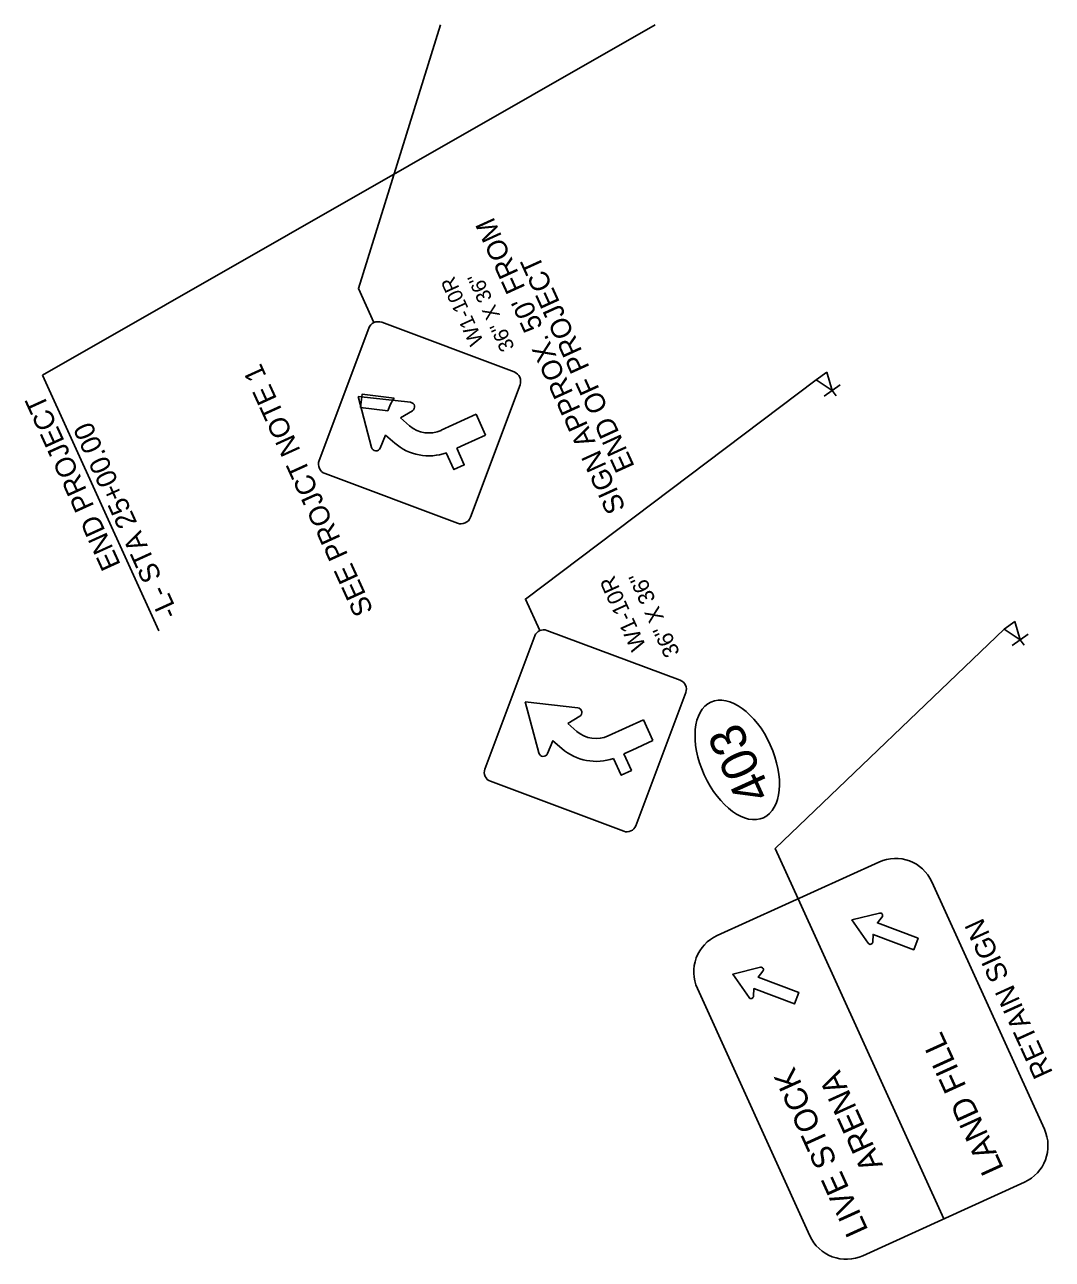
# Model space of a CAD drawing. Extents: x 2096999 to 2102576, y 682920 to 687015.
# Drawn here: x 2101573.8 to 2101932.4, y 683918.8 to 684349.7 of the extents above; entities that cross this region are included whole.
import ezdxf

# ---------------------------------------------------------------- set-up
doc = ezdxf.new("R2010")
doc.units = 0
doc.layers.add('Default', color=7, linetype='Continuous')
doc.layers.add('Prop Horizontal Alignment Station Label', color=7, linetype='Continuous')

msp = doc.modelspace()

# ---------------------------------------------------------------- linework, layer by layer
at = {"layer": 'Default'}
for p, q in [((2101693.88, 684243.79), (2101676.56, 684197.58)), ((2101744.62, 684228.53), (2101698.41, 684245.85)), ((2101850.01, 684225.82), (2101853.73, 684228.49)), ((2101855.64, 684222.11), (2101850.01, 684225.82)), ((2101853.73, 684228.49), (2101855.64, 684222.11)), ((2101729.36, 684177.79), (2101746.68, 684224)), ((2101852.85, 684220.11), (2101858.38, 684224.08)), ((2101855.64, 684222.11), (2101856.99, 684220.23)), ((2101690.14, 684220.01), (2101708.49, 684217.93)), ((2101694.88, 684202.17), (2101690.14, 684220.01)), ((2101708.49, 684217.93), (2101690.14, 684220.01)), ((2101690.14, 684220.01), (2101694.88, 684202.17)), ((2101708.49, 684217.93), (2101690.14, 684220.01)), ((2101690.14, 684220.01), (2101694.88, 684202.17)), ((2101709.14, 684214.99), (2101704.99, 684212.47)), ((2101704.99, 684212.47), (2101709.14, 684214.99)), ((2101704.99, 684212.47), (2101709.14, 684214.99)), ((2101704.99, 684212.47), (2101708.15, 684209.72)), ((2101708.15, 684209.72), (2101704.99, 684212.47)), ((2101708.15, 684209.72), (2101704.99, 684212.47)), ((2101719.11, 684208.15), (2101731.38, 684213.74)), ((2101731.38, 684213.74), (2101719.11, 684208.15)), ((2101731.38, 684213.74), (2101719.11, 684208.15)), ((2101731.38, 684213.74), (2101734.68, 684206.48)), ((2101734.68, 684206.48), (2101731.38, 684213.74)), ((2101734.68, 684206.48), (2101731.38, 684213.74)), ((2101697.88, 684201.95), (2101699.78, 684206.44)), ((2101699.78, 684206.44), (2101702.94, 684203.69)), ((2101708.99, 684207.72), (2101708.98, 684207.7)), ((2101734.68, 684206.48), (2101727.4, 684203.16)), ((2101727.4, 684203.16), (2101734.68, 684206.48)), ((2101727.4, 684203.16), (2101734.68, 684206.48)), ((2101694.88, 684202.17), (2101694.88, 684202.17)), ((2101694.88, 684202.17), (2101694.88, 684202.17)), ((2101694.88, 684202.17), (2101694.88, 684202.17)), ((2101727.4, 684203.16), (2101724.57, 684201.87)), ((2101724.57, 684201.87), (2101727.4, 684203.16)), ((2101724.57, 684201.87), (2101727.4, 684203.16)), ((2101678.62, 684193.05), (2101724.83, 684175.73)), ((2101915.59, 684138.73), (2101919.31, 684141.4)), ((2101919.31, 684141.4), (2101921.22, 684135.02)), ((2101802.6, 684120.9), (2101756.07, 684138.34)), ((2101921.22, 684135.02), (2101915.59, 684138.73)), ((2101918.43, 684133.02), (2101923.96, 684136.99)), ((2101921.22, 684135.02), (2101922.57, 684133.14)), ((2101753.24, 684095.53), (2101748.5, 684113.36)), ((2101748.5, 684113.36), (2101766.85, 684111.28)), ((2101766.85, 684111.28), (2101748.5, 684113.36)), ((2101748.5, 684113.36), (2101753.24, 684095.53)), ((2101767.5, 684108.34), (2101763.35, 684105.82)), ((2101763.35, 684105.82), (2101767.5, 684108.34)), ((2101763.35, 684105.82), (2101766.51, 684103.08)), ((2101766.51, 684103.08), (2101763.35, 684105.82)), ((2101777.47, 684101.51), (2101789.74, 684107.09)), ((2101789.74, 684107.09), (2101777.47, 684101.51)), ((2101789.74, 684107.09), (2101793.04, 684099.84)), ((2101793.04, 684099.84), (2101789.74, 684107.09)), ((2101767.35, 684101.08), (2101767.34, 684101.05)), ((2101785.76, 684096.52), (2101782.93, 684095.23)), ((2101782.93, 684095.23), (2101785.76, 684096.52)), ((2101793.04, 684099.84), (2101785.76, 684096.52)), ((2101785.76, 684096.52), (2101793.04, 684099.84)), ((2101753.24, 684095.52), (2101753.24, 684095.53)), ((2101753.24, 684095.53), (2101753.24, 684095.52)), ((2101843.71, 684044.64), (2101835.75, 684062.14)), ((2101894.54, 683932.9), (2101843.71, 684044.64))]:
    msp.add_line(p, q, dxfattribs=at)
for points in [[(2101695.71, 684245.76), (2101690.3, 684257.66), (2101718.91, 684349.73)], [(2101753.56, 684138.25), (2101748.57, 684149.24), (2101850.01, 684225.82)], [(2101702.7, 684219.42), (2101691.64, 684220.79), (2101691.06, 684216.14), (2101700.59, 684214.95)], [(2101702.94, 684203.69), (2101699.78, 684206.44), (2101697.88, 684201.95)], [(2101697.88, 684201.95), (2101699.78, 684206.44), (2101702.94, 684203.69)], [(2101720.96, 684200.3), (2101723.63, 684194.43), (2101727.21, 684196.06), (2101724.57, 684201.87)], [(2101720.96, 684200.3), (2101723.63, 684194.43), (2101727.21, 684196.06), (2101724.57, 684201.87)], [(2101720.96, 684200.3), (2101723.63, 684194.43), (2101727.21, 684196.06), (2101724.57, 684201.87)], [(2101751.85, 684136.42), (2101734.41, 684089.89)], [(2101835.75, 684062.14), (2101835.75, 684062.14), (2101915.59, 684138.73)], [(2101787.09, 684070.15), (2101804.52, 684116.68)], [(2101761.3, 684097.04), (2101758.14, 684099.79), (2101756.24, 684095.31)], [(2101756.24, 684095.31), (2101758.14, 684099.79), (2101761.3, 684097.04)], [(2101779.32, 684093.66), (2101781.99, 684087.79), (2101785.57, 684089.42), (2101782.93, 684095.23)], [(2101779.32, 684093.66), (2101781.99, 684087.79), (2101785.57, 684089.42), (2101782.93, 684095.23)], [(2101736.33, 684085.66), (2101782.86, 684068.23)], [(2101815.48, 684031.8), (2101871.95, 684057.48)], [(2101890.4, 684050.57), (2101929.69, 683964.19)], [(2101868.21, 684029.11), (2101862.5, 684037.25), (2101872.16, 684039.65)], [(2101868.21, 684029.11), (2101862.5, 684037.25), (2101872.16, 684039.65)], [(2101868.21, 684029.11), (2101862.5, 684037.25), (2101872.16, 684039.65)], [(2101873.04, 684038.29), (2101871.4, 684036.2), (2101885.58, 684030.89), (2101884.08, 684026.88), (2101869.9, 684032.2), (2101869.76, 684029.55)], [(2101873.04, 684038.29), (2101871.4, 684036.2), (2101885.58, 684030.89), (2101884.08, 684026.88), (2101869.9, 684032.2), (2101869.76, 684029.55)], [(2101873.04, 684038.29), (2101871.4, 684036.2), (2101885.58, 684030.89), (2101884.08, 684026.88), (2101869.9, 684032.2), (2101869.76, 684029.55)], [(2101826.61, 684010.19), (2101820.91, 684018.33), (2101830.56, 684020.73)], [(2101826.61, 684010.19), (2101820.91, 684018.33), (2101830.56, 684020.73)], [(2101826.61, 684010.19), (2101820.91, 684018.33), (2101830.56, 684020.73)], [(2101831.44, 684019.37), (2101829.81, 684017.28), (2101843.98, 684011.97), (2101842.48, 684007.96), (2101828.3, 684013.28), (2101828.17, 684010.63)], [(2101831.44, 684019.37), (2101829.81, 684017.28), (2101843.98, 684011.97), (2101842.48, 684007.96), (2101828.3, 684013.28), (2101828.17, 684010.63)], [(2101831.44, 684019.37), (2101829.81, 684017.28), (2101843.98, 684011.97), (2101842.48, 684007.96), (2101828.3, 684013.28), (2101828.17, 684010.63)], [(2101847.85, 683926.97), (2101808.57, 684013.35)], [(2101922.77, 683945.74), (2101866.3, 683920.06)]]:
    msp.add_lwpolyline(points, dxfattribs=at)
for centre, radius, start, end in [((2101697.17, 684242.55), 3.52, 69.458, 159.458), ((2101743.38, 684225.24), 3.52, 339.458, 69.458), ((2101718.47, 684209.24), 18.77, 147.1671, 162.2946), ((2101708.31, 684216.35), 1.59, 301.3774, 83.5059), ((2101708.31, 684216.35), 1.59, 301.3774, 83.5059), ((2101708.31, 684216.35), 1.59, 301.3774, 83.5059), ((2101714.86, 684217.48), 10.26, 229.1817, 294.4888), ((2101714.86, 684217.48), 10.26, 229.1817, 294.4888), ((2101714.86, 684217.48), 10.26, 229.1817, 294.4888), ((2101696.42, 684202.58), 1.59, 194.8575, 336.9795), ((2101696.42, 684202.58), 1.59, 194.8575, 336.9795), ((2101696.42, 684202.58), 1.59, 194.8575, 336.9795), ((2101714.86, 684217.48), 18.23, 229.1817, 289.562), ((2101714.86, 684217.48), 18.23, 229.1817, 289.562), ((2101714.86, 684217.48), 18.23, 229.1817, 289.562), ((2101679.86, 684196.34), 3.52, 159.458, 249.458), ((2101726.07, 684179.02), 3.52, 249.458, 339.458), ((2101754.92, 684135.26), 3.28, 69.458, 159.458), ((2101801.45, 684117.83), 3.28, 24.458, 69.458), ((2101801.45, 684117.83), 3.28, 339.458, 24.458), ((2101766.67, 684109.7), 1.59, 301.3774, 83.5059), ((2101766.67, 684109.7), 1.59, 301.3774, 83.5059), ((2101773.22, 684110.84), 10.26, 229.1817, 294.4888), ((2101773.22, 684110.84), 10.26, 229.1817, 294.4888), ((2101773.22, 684110.84), 18.23, 229.1817, 289.562), ((2101773.22, 684110.84), 18.23, 229.1817, 289.562), ((2101754.78, 684095.93), 1.59, 194.8575, 336.9795), ((2101754.78, 684095.93), 1.59, 194.8575, 336.9795), ((2101737.49, 684088.73), 3.28, 159.445, 204.4515), ((2101737.49, 684088.73), 3.28, 204.4515, 249.458), ((2101784.01, 684071.3), 3.28, 249.458, 339.458), ((2101877.72, 684044.8), 13.93, 24.458, 114.458), ((2101872.36, 684038.81), 0.856, 321.857, 103.9072), ((2101872.36, 684038.81), 0.856, 321.857, 103.9072), ((2101872.36, 684038.81), 0.856, 321.857, 103.9072), ((2101821.25, 684019.12), 13.93, 114.458, 204.458), ((2101868.91, 684029.6), 0.856, 215.0087, 357.0589), ((2101868.91, 684029.6), 0.856, 215.0087, 357.0589), ((2101868.91, 684029.6), 0.856, 215.0087, 357.0589), ((2101830.77, 684019.89), 0.856, 321.857, 103.9072), ((2101830.77, 684019.89), 0.856, 321.857, 103.9072), ((2101830.77, 684019.89), 0.856, 321.857, 103.9072), ((2101827.31, 684010.68), 0.856, 215.0087, 357.0589), ((2101827.31, 684010.68), 0.856, 215.0087, 357.0589), ((2101827.31, 684010.68), 0.856, 215.0087, 357.0589), ((2101917, 683958.42), 13.93, 294.458, 24.458), ((2101860.54, 683932.74), 13.93, 204.458, 294.458)]:
    msp.add_arc(centre, radius, start, end, dxfattribs=at)
msp.add_ellipse((2101822.49, 684093.13), major_axis=(9.17, -20.19), ratio=0.571429, dxfattribs=at)
at = {"layer": 'Prop Horizontal Alignment Station Label'}
for p in [(2101793.81, 684349.66), (2101620.61, 684138.18)]:
    msp.add_line(p, (2101580.03, 684227.41), dxfattribs=at)

# ---------------------------------------------------------------- texts
at = {"layer": 'Default'}
for s, height, rotation, p in [("SIGN APPROX. 50' FROM", 7, 114.4888, (2101783.68, 684180.97)), ('END OF PROJECT', 7, 114.4888, (2101786.8, 684195.53)), ('W1-10R', 5.174, 114.458, (2101734.05, 684239.19)), ("36'' X 36''", 5.1742, 114.458, (2101744.88, 684237.09)), ('SEE PROJCT NOTE 1', 7, 114.4888, (2101695.61, 684145.24)), ('W1-10R', 5.625, 114.458, (2101790.8, 684132.77)), ("36'' X 36''", 5.6251, 114.458, (2101802.58, 684130.49)), ('403', 12.516, 114.4239, (2101834.69, 684081.4)), ('RETAIN SIGN', 7, 114.4888, (2101932.76, 683983.93)), ('LAND FILL', 8, 114.458, (2101915.62, 683950.49)), ('LIVE STOCK', 8, 114.458, (2101868.33, 683928.99)), ('ARENA', 8, 114.458, (2101873.4, 683951.65))]:
    msp.add_text(s, height=height, rotation=rotation, dxfattribs=at).set_placement(p)
at = {"layer": 'Prop Horizontal Alignment Station Label'}
for s, p in [('END PROJECT', (2101607.44, 684161.26)), ('-L- STA 25+00.00', (2101627.59, 684144.16))]:
    msp.add_text(s, height=7, rotation=114.458, dxfattribs=at).set_placement(p)

doc.saveas('drawing.dxf')
